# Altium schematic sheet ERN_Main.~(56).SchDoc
size A; SheetNumber: 1; SheetTotal: 4; SPICEModelCacheDBTNACQE: <root> / <DocumentId>DBTNACQE</DocumentId> / <CacheFrame Number="0"> / <Model Name="irf9510" Kind="CKT"> / <Text>*IRF9510  MCE  4-2-96 / *100V  4A  1.2 ohms HEXFET pkg:TO-220 2,1,3 / .SUBCKT IRF9510  10 20 40 40 / M1   1  2  3  3  DMOS L=1U W=1U / RD  10  1  .569 / RS  30  3  31M / RG  20  2  37.5 / CGS  2  3  182P / EGD 12  0  1  2  1 / VFB 14  0  0 / FFB  1  2  VFB  1 / CGD 13 14  231P / R1  13  0  1 / D1  12 13  DLIM / DDG 15 14  DCGD / R2  12 15  1 / D2  15  0  DLIM / DSD 10  3  DSUB / LS  30 40  7.5N / .MODEL DMOS PMOS (LEVEL=3 THETA=60M VMAX=208K ETA=2M VTO=-3 KP=.471) / .MODEL DCGD D (CJO=231P VJ=.6 M=.68) / .MODEL DSUB D (IS=16.6N N=1.5 RS=1.18 BV=100 CJO=327P VJ=.8 M=.42 TT=82N) / .MODEL DLIM D (IS=100U) / .ENDS IRF9510</Text> / </Model> / <Model Name="nmos" Kind="MDL"> / <Text>*Default N-Channel MOSFET / *Pinout: D,G,S / .MODEL NMOS NMOS()</Text> / </Model> / </CacheFrame> / </root>
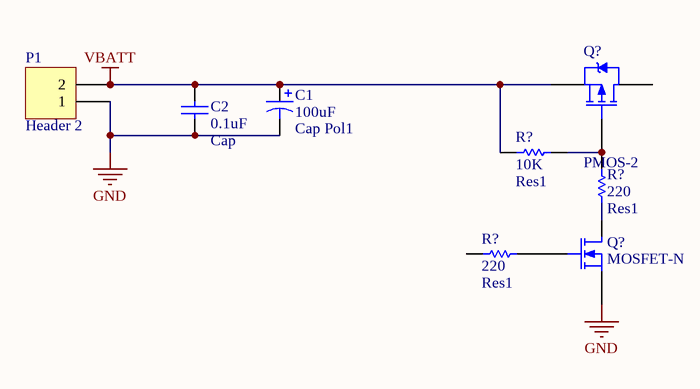
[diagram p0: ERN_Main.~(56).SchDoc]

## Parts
(Parts that share a designator on the sheet are numbered #1, #2 ... from top to bottom, then left to right.)
C1  Cap Pol1  value 100uF  [RB7.6-15]
C2  Cap  value 0.1uF  [RAD-0.3]
P1  Header 2  [HDR1X2]
Q?#1  PMOS-2  [TO-220AB]
Q?#2  MOSFET-N  [E3]
R?#1  Res1  value 10K  [AXIAL-0.3]
R?#2  Res1  value 220  [AXIAL-0.3]
R?#3  Res1  value 220  [AXIAL-0.3]

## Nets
GND: C1.2 C2.1 P1.1 Q?#2.3(S)
VBATT: C1.1 C2.2 P1.2 Q?#1.3(S) R?#1.2
NetQ?#1_1: Q?#1.1(G) R?#1.1 R?#2.1
NetQ?#2_1: Q?#2.1(D) R?#2.2
NetQ?#2_2: Q?#2.2(G) R?#3.1

Not connected (* = marked no-connect by the designer): Q?#1 2(D); R?#3 2

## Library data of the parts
C1 = Cap Pol1: Polarized Capacitor (Radial)
C2 = Cap: Capacitor
P1 = Header 2: Header, 2-Pin
Q?#1 = PMOS-2: P-Channel Power MOSFET; Note: Pin 4 not drawn and electrically connected to Pin 2.
Q?#2 = MOSFET-N: N-Channel MOSFET
R?#1-R?#3 = Res1: Resistor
